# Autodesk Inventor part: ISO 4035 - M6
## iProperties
Created: 2001-08
Part Number: ISO 4035 - M6
Catalog Web Link: file:///D:/Program%20Files/Autodesk/Inventor%205/Content/Iso/index.htm?doNavigateId=83012FF0-6BA1-417C-899B-D5B285169CF3|D3FB09DD3FC14D7E95503048018C615B|true
Description: Hex Nut
Document SubType Name: Standard Catalog Part
Standard: ISO 4035 - M6
Designer: Martin Budgell
Control State: 0
Master: False
Checked Out: False
Length Units: 11269
Angle Units: 11279
Time Units: 11290
Mass Units: 11283
Shininess: 3
Angle Display Precision: 2
Document Length Units: 11269
Document Angle Units: 11279
Document Time Units: 11290
Document Mass Units: 11283
Document Length Units Precision: 3
Document Angle Units Precision: 2
Compacted: True
CLASSIFICATION: 31161727 un/spsc
MANUFACTURER: ISO Standard System
Density: 0.0
Volumn: 0.0
Area: 0.0
PropertySet Name: Model Information
Author: Martin Budgell
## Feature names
1. Base1
